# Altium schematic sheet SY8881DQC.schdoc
size 127 x 101 mm
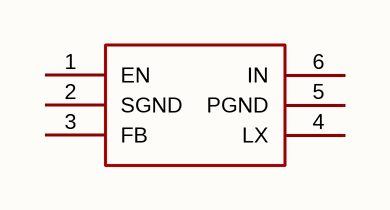
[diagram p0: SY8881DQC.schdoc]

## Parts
U?  sy8881dqc  [DFN-6_L1.5-W1.5-P0.50-BL]  (value not drawn)

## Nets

Not connected (* = marked no-connect by the designer): U? 1(EN) 2(SGND) 3(FB) 4(LX) 5(PGND) 6(IN)

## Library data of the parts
U? = sy8881dqc: 功能类型:降压型;工作电压:2.5V~5.5V;输出电压:600mV~5.5V;输出电流:1A;输出类型:可调;; Manufacturer: Silergy(矽力杰); AddInBom: yes; ModelId: 74a233c6768b4d48ae7baff1158593b1; ModelName: DNF-6_L1.5-W1.5-H0.5-P0.50; ModelTransform: 59.8424,59.055,0,90,0,0,-0.16,-0.235,0; Function: 降压型; Output Current: 1A; Frequency - Switching: 2.5MHz; Synchronous Rectifier: 是; Number of Outputs: 1; Topology: 降压式; Quiescent Current: 40uA; Switch tube (built-in/external): 内置; Output Type: 可调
